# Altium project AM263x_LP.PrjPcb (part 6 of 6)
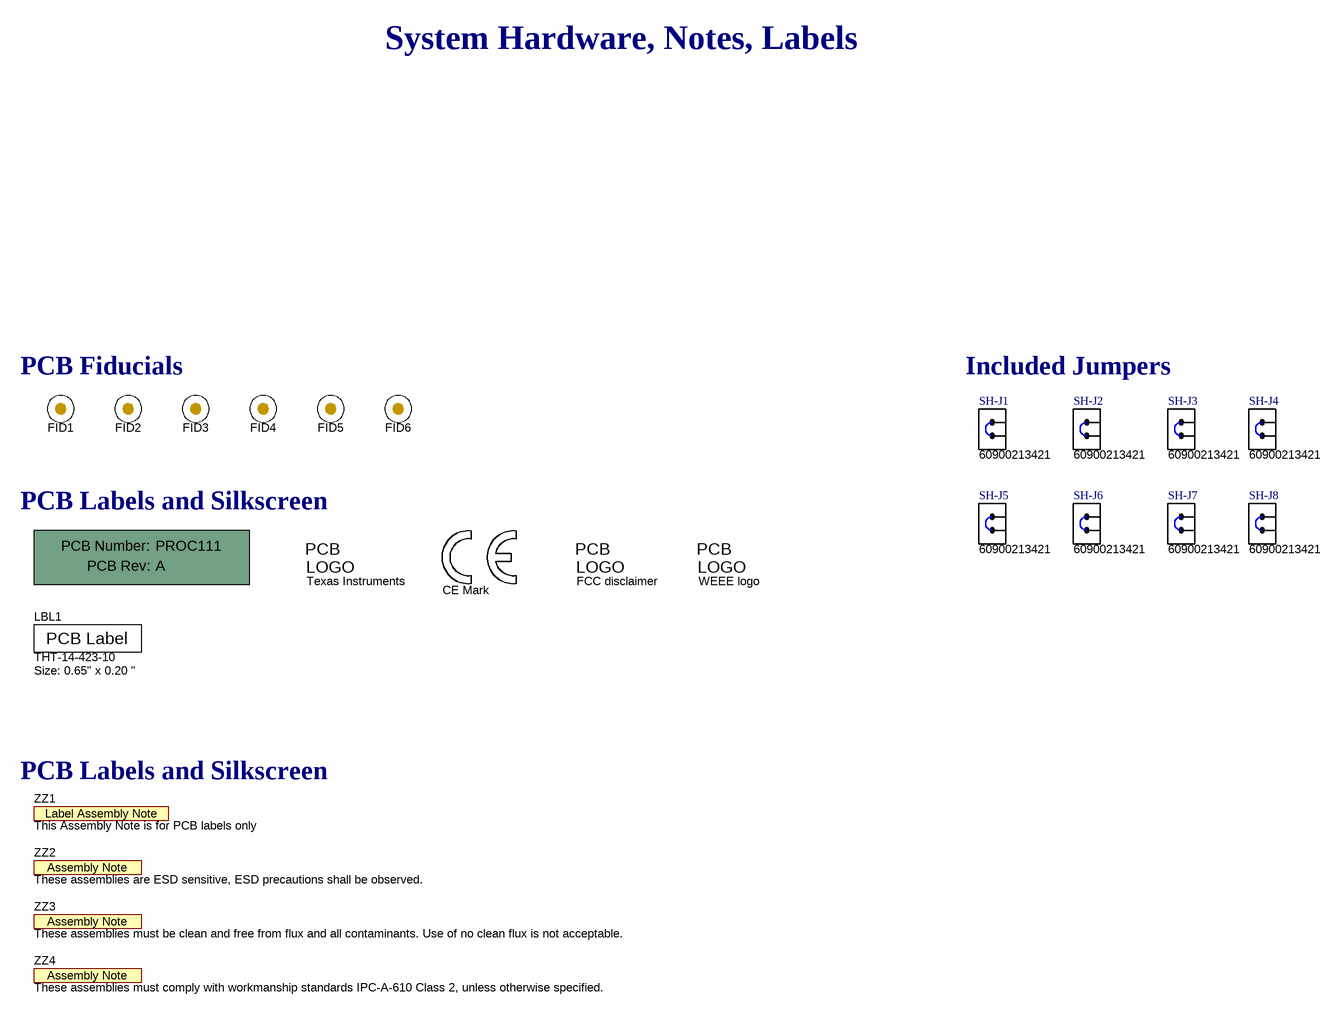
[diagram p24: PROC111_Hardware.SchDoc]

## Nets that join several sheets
GND: PROC111_System_Power_1 (34 pins), PROC111_System_Power_2 (48 pins), PROC111_AM263x_1_Power (147 pins), PROC111_AM263x_2_Clock_Reset_Boot_JTAG (30 pins), PROC111_AM263x_3_QSPI_MMC (17 pins), PROC111_AM263x_4_ADC_DAC (35 pins), PROC111_AM263x_6_RGMII_MII (C100.1 U17.3), PROC111_AM263x_7_PRU (11 pins), PROC111_Push_Buttons (13 pins), PROC111_Test_Automation (19 pins), PROC111_Ehernet_PHY_1 (41 pins), PROC111_Ehernet_PHY_2 (35 pins), PROC111_Ehernet_RJ45_1 (10 pins), PROC111_Ehernet_RJ45_2 (10 pins), PROC111_Boosterpack_Headers (12 pins), PROC111_Breakout_Headers (31 pins), PROC111_XDS110_2 (7 pins), PROC111_LED (14 pins)
GND_XDS: PROC111_XDS110_1 (14 pins), PROC111_XDS110_2 (44 pins)
VBUS_XDS_5V0: PROC111_XDS110_1 (7 pins), PROC111_XDS110_2 (R132.2 R136.2)
VDD_AM263_1V2: PROC111_System_Power_2 (7 pins), PROC111_AM263x_1_Power (49 pins)
VDD_ETH_1V1: PROC111_System_Power_2 (6 pins), PROC111_Ehernet_PHY_1 (FB3.1), PROC111_Ehernet_PHY_2 (FB5.1)
VDD_ETH_2V5: PROC111_System_Power_2 (6 pins), PROC111_Ehernet_PHY_1 (FB4.1), PROC111_Ehernet_PHY_2 (FB6.1)
VDD_XDS3V3: PROC111_XDS110_1 (7 pins), PROC111_XDS110_2 (36 pins)
VDDA_AM263_1V8_LDO: PROC111_AM263x_1_Power (9 pins), PROC111_AM263x_4_ADC_DAC (S1.1)
VPP_AM263_1V7: PROC111_System_Power_2 (C253.1 R372.2 U53.5), PROC111_AM263x_1_Power (R376.2)
VSYS_3V3: PROC111_System_Power_1 (J12.1), PROC111_System_Power_2 (11 pins), PROC111_AM263x_1_Power (20 pins), PROC111_AM263x_2_Clock_Reset_Boot_JTAG (14 pins), PROC111_AM263x_Serial_Connectivity (R175.2 R176.2), PROC111_AM263x_3_QSPI_MMC (15 pins), PROC111_AM263x_5_ePWM_eQEP_FSI (R55.2 R56.2), PROC111_AM263x_6_RGMII_MII (C100.2 R63.2 R64.2 U17.8), PROC111_AM263x_7_PRU (14 pins), PROC111_Push_Buttons (8 pins), PROC111_Test_Automation (U35.1 U35.5), PROC111_Ehernet_PHY_1 (26 pins), PROC111_Ehernet_PHY_2 (18 pins), PROC111_Ehernet_RJ45_1 (R224.1 R226.2 R228.2), PROC111_Ehernet_RJ45_2 (R230.1 R232.2 R234.2), PROC111_Boosterpack_Headers (11 pins), PROC111_Breakout_Headers (8 pins), PROC111_XDS110_2 (6 pins), PROC111_LED (17 pins)
VSYS_5V0: PROC111_System_Power_1 (5 pins), PROC111_System_Power_2 (26 pins), PROC111_AM263x_1_Power (R1.2), PROC111_Breakout_Headers (16 pins), PROC111_LED (R257.2 R265.2 R302.2)
VSYS_TA_3V3: PROC111_AM263x_2_Clock_Reset_Boot_JTAG (12 pins), PROC111_Test_Automation (23 pins), PROC111_LED (R315.2)
VUSB_5V0: PROC111_System_Power_1 (19 pins), PROC111_Test_Automation (C187.1 C188.1 R193.2 U36.2), PROC111_Boosterpack_Headers (J10.1 J14.1)
ADC_EXT_VREF: PROC111_AM263x_4_ADC_DAC (S2.3 S2.6), PROC111_Breakout_Headers (J17.2)
AM263_ADC0_AIN0: PROC111_AM263x_4_ADC_DAC (R340.1 U12.1 U12.10), PROC111_Boosterpack_Headers (J1/J3.23)
AM263_ADC0_AIN1: PROC111_AM263x_4_ADC_DAC (R341.1 U13.2 U13.9), PROC111_Boosterpack_Headers (J1/J3.28)
AM263_ADC0_AIN2: PROC111_AM263x_4_ADC_DAC (R342.1), PROC111_Boosterpack_Headers (U52.32)
AM263_ADC0_AIN2_LIN1_TXD: PROC111_AM263x_4_ADC_DAC (U14.5 U14.6), PROC111_Boosterpack_Headers (J5/J7.66 U52.7)
AM263_ADC0_AIN3: PROC111_AM263x_4_ADC_DAC (R343.1 U13.5 U13.6), PROC111_Boosterpack_Headers (J1/J3.2)
AM263_ADC1_AIN0: PROC111_AM263x_4_ADC_DAC (R344.1 U12.2 U12.9), PROC111_Boosterpack_Headers (J1/J3.24)
AM263_ADC1_AIN1: PROC111_AM263x_4_ADC_DAC (R345.1 U13.4 U13.7), PROC111_Boosterpack_Headers (J1/J3.29)
AM263_ADC1_AIN2: PROC111_AM263x_4_ADC_DAC (R346.1), PROC111_Boosterpack_Headers (U52.29)
AM263_ADC1_AIN2_SDFM0_D2: PROC111_AM263x_4_ADC_DAC (U15.1 U15.10), PROC111_Boosterpack_Headers (J5/J7.67 U52.11)
AM263_ADC1_AIN3: PROC111_AM263x_4_ADC_DAC (D16.1 R347.1), PROC111_Boosterpack_Headers (J1/J3.6)
AM263_ADC2_AIN0: PROC111_AM263x_4_ADC_DAC (R348.1 U12.4 U12.7), PROC111_Boosterpack_Headers (J1/J3.25)
AM263_ADC2_AIN1: PROC111_AM263x_4_ADC_DAC (R349.1), PROC111_Boosterpack_Headers (U52.38)
AM263_ADC2_AIN1_MCAN1_RX: PROC111_AM263x_4_ADC_DAC (U14.1 U14.10), PROC111_Boosterpack_Headers (J5/J7.63 U52.4)
AM263_ADC2_AIN2: PROC111_AM263x_4_ADC_DAC (R350.1), PROC111_Boosterpack_Headers (U52.27)
AM263_ADC2_AIN2_SDFM0_CLK2: PROC111_AM263x_4_ADC_DAC (U15.2 U15.9), PROC111_Boosterpack_Headers (J5/J7.68 U52.12)
AM263_ADC2_AIN3: PROC111_AM263x_4_ADC_DAC (R351.1 U15.5 U15.6), PROC111_Boosterpack_Headers (J5/J7.42)
AM263_ADC3_AIN0: PROC111_AM263x_4_ADC_DAC (R352.1 U12.5 U12.6), PROC111_Boosterpack_Headers (J1/J3.26)
AM263_ADC3_AIN1: PROC111_AM263x_4_ADC_DAC (R353.1), PROC111_Boosterpack_Headers (U52.36)
AM263_ADC3_AIN1_MCAN1_TX: PROC111_AM263x_4_ADC_DAC (U14.2 U14.9), PROC111_Boosterpack_Headers (J5/J7.64 U52.5)
AM263_ADC3_AIN2: PROC111_AM263x_4_ADC_DAC (R354.1), PROC111_Boosterpack_Headers (U52.25)
AM263_ADC3_AIN2_SDFM0_D3: PROC111_AM263x_4_ADC_DAC (U15.4 U15.7), PROC111_Boosterpack_Headers (J5/J7.69 U52.13)
AM263_ADC3_AIN3: PROC111_AM263x_4_ADC_DAC (D15.1 R355.1), PROC111_Boosterpack_Headers (J5/J7.46)
AM263_ADC4_AIN0: PROC111_AM263x_4_ADC_DAC (R356.1 R358.1 U13.1 U13.10), PROC111_Boosterpack_Headers (J1/J3.27)
AM263_ADC4_AIN1: PROC111_AM263x_4_ADC_DAC (R357.1 R359.1), PROC111_Boosterpack_Headers (U52.34)
AM263_ADC4_AIN1_LIN1_RXD: PROC111_AM263x_4_ADC_DAC (U14.4 U14.7), PROC111_Boosterpack_Headers (J5/J7.65 U52.6)
AM263_BP_MUX_SEL_GPIO63: PROC111_AM263x_5_ePWM_eQEP_FSI (U1.G4), PROC111_Boosterpack_Headers (5 pins)
AM263_CAN_STB_GPIO51: PROC111_AM263x_5_ePWM_eQEP_FSI (U1.D1), PROC111_Breakout_Headers (R248.2)
AM263_CLKOUT0: PROC111_AM263x_2_Clock_Reset_Boot_JTAG (R4.2 TP1.1), PROC111_Ehernet_PHY_1 (R118.1)
AM263_DAC_OUT1: PROC111_AM263x_4_ADC_DAC (R45.1), PROC111_Boosterpack_Headers (J1/J3.30)
AM263_DAC_OUT2: PROC111_AM263x_4_ADC_DAC (R3.1), PROC111_Boosterpack_Headers (U52.23)
AM263_EPWM0_A: PROC111_AM263x_5_ePWM_eQEP_FSI (R46.1), PROC111_Boosterpack_Headers (J2/J4.11)
AM263_EPWM0_B: PROC111_AM263x_5_ePWM_eQEP_FSI (R47.1), PROC111_Boosterpack_Headers (J6/J8.59)
AM263_EPWM1_A: PROC111_AM263x_5_ePWM_eQEP_FSI (R48.1), PROC111_Boosterpack_Headers (J2/J4.37)
AM263_EPWM1_B: PROC111_AM263x_5_ePWM_eQEP_FSI (R49.1), PROC111_Boosterpack_Headers (J2/J4.38)
AM263_EPWM2_A: PROC111_AM263x_5_ePWM_eQEP_FSI (R50.1), PROC111_Boosterpack_Headers (J2/J4.39)
AM263_EPWM2_B: PROC111_AM263x_5_ePWM_eQEP_FSI (R51.1), PROC111_Boosterpack_Headers (J2/J4.40)
AM263_EPWM3_A: PROC111_AM263x_5_ePWM_eQEP_FSI (R52.1), PROC111_Boosterpack_Headers (J6/J8.77)
AM263_EPWM3_B: PROC111_AM263x_5_ePWM_eQEP_FSI (R53.1), PROC111_Boosterpack_Headers (J6/J8.78)
AM263_EPWM9_A: PROC111_AM263x_5_ePWM_eQEP_FSI (R9.1), PROC111_Boosterpack_Headers (J6/J8.75)
AM263_EPWM9_B: PROC111_AM263x_5_ePWM_eQEP_FSI (R12.1), PROC111_Boosterpack_Headers (J6/J8.76)
AM263_EPWM11_A: PROC111_AM263x_5_ePWM_eQEP_FSI (R13.1), PROC111_Boosterpack_Headers (J6/J8.51)
AM263_EPWM11_B: PROC111_AM263x_5_ePWM_eQEP_FSI (R99.1), PROC111_Boosterpack_Headers (J6/J8.52)
AM263_EPWM12_A: PROC111_AM263x_5_ePWM_eQEP_FSI (R280.1), PROC111_Boosterpack_Headers (J6/J8.53)
AM263_EPWM12_B: PROC111_AM263x_5_ePWM_eQEP_FSI (R281.1), PROC111_Boosterpack_Headers (J6/J8.57)
AM263_EPWM13_A: PROC111_AM263x_5_ePWM_eQEP_FSI (R59.1), PROC111_Boosterpack_Headers (J6/J8.79)
AM263_EPWM13_B: PROC111_AM263x_5_ePWM_eQEP_FSI (R60.1), PROC111_Boosterpack_Headers (J6/J8.80)
AM263_EPWM14_A: PROC111_AM263x_5_ePWM_eQEP_FSI (R282.1), PROC111_Boosterpack_Headers (J2/J4.35)
AM263_EPWM14_B: PROC111_AM263x_5_ePWM_eQEP_FSI (R283.1), PROC111_Boosterpack_Headers (J2/J4.36)
AM263_EPWM15_A: PROC111_AM263x_5_ePWM_eQEP_FSI (R284.1), PROC111_Boosterpack_Headers (J2/J4.34)
AM263_EPWM15_B: PROC111_AM263x_5_ePWM_eQEP_FSI (R285.1), PROC111_Boosterpack_Headers (J5/J7.45)
AM263_EQEP0_A: PROC111_AM263x_5_ePWM_eQEP_FSI (U1.B14), PROC111_Breakout_Headers (R328.1)
AM263_EQEP0_B: PROC111_AM263x_5_ePWM_eQEP_FSI (U1.A14), PROC111_Breakout_Headers (R329.1)
AM263_EQEP0_INDEX: PROC111_AM263x_5_ePWM_eQEP_FSI (U1.D11), PROC111_Breakout_Headers (R330.1)
AM263_EQEP0_STROBE: PROC111_AM263x_5_ePWM_eQEP_FSI (U1.C12), PROC111_Breakout_Headers (R331.1)
AM263_EQEP2_A: PROC111_AM263x_Serial_Connectivity (U1.B13), PROC111_Breakout_Headers (R332.1)
AM263_EQEP2_B: PROC111_AM263x_Serial_Connectivity (U1.A13), PROC111_Breakout_Headers (R333.1)
AM263_EQEP2_INDEX: PROC111_AM263x_Serial_Connectivity (U1.A12), PROC111_Breakout_Headers (R334.1)
AM263_EQEP2_STROBE: PROC111_AM263x_Serial_Connectivity (U1.B12), PROC111_Breakout_Headers (R335.1)
AM263_FSIRX1_CLK: PROC111_AM263x_5_ePWM_eQEP_FSI (U1.E1), PROC111_Breakout_Headers (J23.1)
AM263_FSIRX1_DATA0: PROC111_AM263x_5_ePWM_eQEP_FSI (U1.F3), PROC111_Breakout_Headers (J23.5)
AM263_FSIRX1_DATA1: PROC111_AM263x_5_ePWM_eQEP_FSI (U1.F4), PROC111_Breakout_Headers (J23.7)
AM263_FSITX1_CLK: PROC111_AM263x_5_ePWM_eQEP_FSI (R54.1), PROC111_Breakout_Headers (J23.2)
AM263_FSITX1_DATA0: PROC111_AM263x_5_ePWM_eQEP_FSI (R57.1), PROC111_Breakout_Headers (J23.6)
AM263_FSITX1_DATA1: PROC111_AM263x_5_ePWM_eQEP_FSI (R58.1), PROC111_Breakout_Headers (J23.8)
AM263_I2C1_SCL: PROC111_AM263x_2_Clock_Reset_Boot_JTAG (U16.6), PROC111_AM263x_Serial_Connectivity (R175.1 U1.D7), PROC111_Boosterpack_Headers (J5/J7.49), PROC111_LED (U48.15)
AM263_I2C1_SDA: PROC111_AM263x_2_Clock_Reset_Boot_JTAG (U16.5), PROC111_AM263x_Serial_Connectivity (R176.1 U1.C8), PROC111_Boosterpack_Headers (J5/J7.50), PROC111_LED (U48.2)
AM263_I2C3_SCL: PROC111_AM263x_5_ePWM_eQEP_FSI (R55.1 U1.H2), PROC111_Test_Automation (U35.2), PROC111_Boosterpack_Headers (J1/J3.9)
AM263_I2C3_SDA: PROC111_AM263x_5_ePWM_eQEP_FSI (R56.1 U1.G3), PROC111_Test_Automation (U35.3), PROC111_Boosterpack_Headers (J1/J3.10)
AM263_ICSSM_MII0_COL: PROC111_AM263x_7_PRU (U49.11), PROC111_Ehernet_PHY_2 (R207.1 R219.2 U37.45), PROC111_Ehernet_RJ45_2 (R231.2)
AM263_ICSSM_MII0_RXCLK: PROC111_AM263x_7_PRU (U23.32), PROC111_Ehernet_PHY_2 (R196.1)
AM263_ICSSM_MII0_RXD0: PROC111_AM263x_7_PRU (U23.41), PROC111_Ehernet_PHY_2 (R198.1 R203.1 R215.2)
AM263_ICSSM_MII0_RXD1: PROC111_AM263x_7_PRU (U23.39), PROC111_Ehernet_PHY_2 (R199.1 R204.1 R216.2)
AM263_ICSSM_MII0_RXD2: PROC111_AM263x_7_PRU (U23.38), PROC111_Ehernet_PHY_2 (R200.1 R210.1 R222.2)
AM263_ICSSM_MII0_RXD3: PROC111_AM263x_7_PRU (U23.36), PROC111_Ehernet_PHY_2 (R201.1 R211.1 R223.2)
AM263_ICSSM_MII0_RXDV: PROC111_AM263x_7_PRU (U23.34), PROC111_Ehernet_PHY_2 (R197.1 R205.1 R217.2)
AM263_ICSSM_MII0_RXER: PROC111_AM263x_7_PRU (U49.2), PROC111_Ehernet_PHY_2 (R206.1 R218.2 U37.46), PROC111_Ehernet_RJ45_2 (R235.2)
AM263_ICSSM_MII0_RXLINK: PROC111_AM263x_7_PRU (U49.5), PROC111_Ehernet_PHY_2 (R208.1 R220.2 U37.47), PROC111_Ehernet_RJ45_2 (R233.2)
AM263_ICSSM_MII0_TXCLK: PROC111_AM263x_7_PRU (U23.19), PROC111_Ehernet_PHY_2 (U37.29)
AM263_ICSSM_MII0_TXD0: PROC111_AM263x_7_PRU (U23.29), PROC111_Ehernet_PHY_2 (U37.28)
AM263_ICSSM_MII0_TXD1: PROC111_AM263x_7_PRU (U23.27), PROC111_Ehernet_PHY_2 (U37.27)
AM263_ICSSM_MII0_TXD2: PROC111_AM263x_7_PRU (U23.25), PROC111_Ehernet_PHY_2 (U37.26)
AM263_ICSSM_MII0_TXD3: PROC111_AM263x_7_PRU (U23.23), PROC111_Ehernet_PHY_2 (U37.25)
AM263_ICSSM_MII0_TXEN: PROC111_AM263x_7_PRU (U23.21), PROC111_Ehernet_PHY_2 (U37.37)
AM263_ICSSM_MII1_COL: PROC111_AM263x_7_PRU (U1.C18), PROC111_Ehernet_PHY_1 (R112.1 R124.2 U22.45), PROC111_Ehernet_RJ45_1 (R225.2)
AM263_ICSSM_MII1_RXCLK: PROC111_AM263x_7_PRU (U1.E16), PROC111_Ehernet_PHY_1 (U50.31)
AM263_ICSSM_MII1_RXD0: PROC111_AM263x_7_PRU (U1.F18), PROC111_Ehernet_PHY_1 (U50.42)
AM263_ICSSM_MII1_RXD1: PROC111_AM263x_7_PRU (U1.G16), PROC111_Ehernet_PHY_1 (U50.40)
AM263_ICSSM_MII1_RXD2: PROC111_AM263x_7_PRU (U1.E17), PROC111_Ehernet_PHY_1 (U50.37)
AM263_ICSSM_MII1_RXD3: PROC111_AM263x_7_PRU (U1.E18), PROC111_Ehernet_PHY_1 (U50.35)
AM263_ICSSM_MII1_RXDV: PROC111_AM263x_7_PRU (U1.F16), PROC111_Ehernet_PHY_1 (U50.33)
AM263_ICSSM_MII1_RXER: PROC111_AM263x_7_PRU (U1.F15), PROC111_Ehernet_PHY_1 (R111.1 R123.2 U22.46), PROC111_Ehernet_RJ45_1 (R229.2)
AM263_ICSSM_MII1_RXLINK: PROC111_AM263x_7_PRU (U1.D18), PROC111_Ehernet_PHY_1 (R110.1 R122.2 U22.47), PROC111_Ehernet_RJ45_1 (R227.2)
AM263_ICSSM_MII1_TXCLK: PROC111_AM263x_7_PRU (R86.1), PROC111_Ehernet_PHY_1 (U50.18)
AM263_ICSSM_MII1_TXD0: PROC111_AM263x_7_PRU (R81.1), PROC111_Ehernet_PHY_1 (U50.28)
AM263_ICSSM_MII1_TXD1: PROC111_AM263x_7_PRU (R82.1), PROC111_Ehernet_PHY_1 (U50.26)
AM263_ICSSM_MII1_TXD2: PROC111_AM263x_7_PRU (R83.1), PROC111_Ehernet_PHY_1 (U50.24)
AM263_ICSSM_MII1_TXD3: PROC111_AM263x_7_PRU (R84.1), PROC111_Ehernet_PHY_1 (U50.22)
AM263_ICSSM_MII1_TXEN: PROC111_AM263x_7_PRU (R85.1), PROC111_Ehernet_PHY_1 (U50.20)
AM263_IEP0_EDC_SYNC_OUT0: PROC111_AM263x_7_PRU (R88.1), PROC111_Boosterpack_Headers (J6/J8.72)
AM263_IEP0_EDIO_DATA_IN_OUT31: PROC111_AM263x_7_PRU (R87.1), PROC111_Boosterpack_Headers (J6/J8.71)
AM263_INT1_PB_GPIO123: PROC111_AM263x_8_SDFM (U1.D14), PROC111_Push_Buttons (U34.4)
AM263_LED_ENABLE_GPIO25: PROC111_AM263x_Serial_Connectivity (U1.C7), PROC111_LED (R278.2 U48.8)
AM263_LED_GPIO26: PROC111_AM263x_Serial_Connectivity (U1.B7), PROC111_LED (R303.1 R304.2)
AM263_LIN1_RXD: PROC111_AM263x_Serial_Connectivity (U1.A9), PROC111_Boosterpack_Headers (U52.33)
AM263_LIN1_TXD: PROC111_AM263x_Serial_Connectivity (R297.1), PROC111_Boosterpack_Headers (U52.31)
AM263_LIN2_RXD: PROC111_AM263x_Serial_Connectivity (U1.B8), PROC111_Boosterpack_Headers (U52.41)
AM263_LIN2_TXD: PROC111_AM263x_Serial_Connectivity (R166.1), PROC111_Boosterpack_Headers (U52.39)
AM263_MCAN0_RX: PROC111_AM263x_Serial_Connectivity (U1.M1), PROC111_Breakout_Headers (R249.1)
AM263_MCAN0_TX: PROC111_AM263x_Serial_Connectivity (R167.1), PROC111_Breakout_Headers (R245.1)
AM263_MCAN1_RX: PROC111_AM263x_Serial_Connectivity (U1.L2), PROC111_Boosterpack_Headers (U52.37)
AM263_MCAN1_TX: PROC111_AM263x_Serial_Connectivity (R168.1), PROC111_Boosterpack_Headers (U52.35)
AM263_MUX_EN_GPIO58: PROC111_AM263x_5_ePWM_eQEP_FSI (U1.F1), PROC111_AM263x_7_PRU (R288.2 R290.2 U23.8 U46.2), PROC111_Boosterpack_Headers (U52.8)
AM263_PORZ_PB: PROC111_AM263x_2_Clock_Reset_Boot_JTAG (U2.1), PROC111_Push_Buttons (U34.6)
AM263_PR0_MDIO0_MDC: PROC111_AM263x_6_RGMII_MII (U17.2), PROC111_AM263x_7_PRU (R71.1 R73.1)
AM263_PR0_MDIO0_MDIO: PROC111_AM263x_6_RGMII_MII (U17.4), PROC111_AM263x_7_PRU (R72.1 R74.1)
AM263_PRU_MUX_SEL_GPIO64: PROC111_AM263x_5_ePWM_eQEP_FSI (U1.J3), PROC111_AM263x_7_PRU (5 pins)
AM263_RESETN_PB: PROC111_AM263x_2_Clock_Reset_Boot_JTAG (R5.1), PROC111_Push_Buttons (R179.1 U33.4)
AM263_RGMII1_RD0: PROC111_AM263x_6_RGMII_MII (U1.U17), PROC111_Ehernet_PHY_1 (U50.41)
AM263_RGMII1_RD1: PROC111_AM263x_6_RGMII_MII (U1.T17), PROC111_Ehernet_PHY_1 (U50.39)
AM263_RGMII1_RD2: PROC111_AM263x_6_RGMII_MII (U1.U18), PROC111_Ehernet_PHY_1 (U50.38)
AM263_RGMII1_RD3: PROC111_AM263x_6_RGMII_MII (U1.T18), PROC111_Ehernet_PHY_1 (U50.36)
AM263_RGMII1_RX_CTL: PROC111_AM263x_6_RGMII_MII (U1.R18), PROC111_Ehernet_PHY_1 (U50.34)
AM263_RGMII1_RXC: PROC111_AM263x_6_RGMII_MII (U1.R17), PROC111_Ehernet_PHY_1 (U50.32)
AM263_RGMII1_TD0: PROC111_AM263x_6_RGMII_MII (R65.1), PROC111_Ehernet_PHY_1 (U50.29)
AM263_RGMII1_TD1: PROC111_AM263x_6_RGMII_MII (R66.1), PROC111_Ehernet_PHY_1 (U50.27)
AM263_RGMII1_TD2: PROC111_AM263x_6_RGMII_MII (R67.1), PROC111_Ehernet_PHY_1 (U50.25)
AM263_RGMII1_TD3: PROC111_AM263x_6_RGMII_MII (R68.1), PROC111_Ehernet_PHY_1 (U50.23)
AM263_RGMII1_TX_CTL: PROC111_AM263x_6_RGMII_MII (R69.1), PROC111_Ehernet_PHY_1 (U50.21)
AM263_RGMII1_TXC: PROC111_AM263x_6_RGMII_MII (R70.1), PROC111_Ehernet_PHY_1 (U50.19)
AM263_SAFETY_ERRORN: PROC111_AM263x_2_Clock_Reset_Boot_JTAG (R258.1 U1.D4), PROC111_LED (R268.1 R272.1)
AM263_SD_ENABLE_GPIO122: PROC111_AM263x_3_QSPI_MMC (U9.2), PROC111_AM263x_8_SDFM (U1.B16)
AM263_SDFM0_CLK1: PROC111_AM263x_8_SDFM (R369.1), PROC111_Boosterpack_Headers (J6/J8.74)
AM263_SDFM0_CLK2: PROC111_AM263x_8_SDFM (R370.1), PROC111_Boosterpack_Headers (U52.26)
AM263_SDFM0_CLK3: PROC111_AM263x_8_SDFM (R371.1), PROC111_Boosterpack_Headers (U52.22)
AM263_SDFM0_D2: PROC111_AM263x_8_SDFM (U1.C13), PROC111_Boosterpack_Headers (U52.28)
AM263_SDFM0_D3: PROC111_AM263x_8_SDFM (U1.C14), PROC111_Boosterpack_Headers (U52.24)
AM263_SFDM0_D1: PROC111_AM263x_8_SDFM (U1.D13), PROC111_Boosterpack_Headers (J6/J8.73)
AM263_SOP0: PROC111_AM263x_2_Clock_Reset_Boot_JTAG (U4.15), PROC111_AM263x_3_QSPI_MMC (R42.2)
AM263_SOP1: PROC111_AM263x_2_Clock_Reset_Boot_JTAG (U4.14), PROC111_AM263x_3_QSPI_MMC (R43.2)
AM263_SOP2: PROC111_AM263x_2_Clock_Reset_Boot_JTAG (U4.13), PROC111_AM263x_Serial_Connectivity (R173.2)
AM263_SOP3: PROC111_AM263x_2_Clock_Reset_Boot_JTAG (U4.12), PROC111_AM263x_Serial_Connectivity (R174.2)
AM263_SPI0_CLK: PROC111_AM263x_Serial_Connectivity (R169.1 R173.1), PROC111_Boosterpack_Headers (U51.2)
AM263_SPI0_CS0: PROC111_AM263x_Serial_Connectivity (U1.C11), PROC111_Boosterpack_Headers (U51.14)
AM263_SPI0_D0: PROC111_AM263x_Serial_Connectivity (R170.1 R174.1), PROC111_Boosterpack_Headers (J2/J4.15)
AM263_SPI0_D1: PROC111_AM263x_Serial_Connectivity (U1.B11), PROC111_Boosterpack_Headers (J2/J4.14)
AM263_SPI1_CLK: PROC111_AM263x_Serial_Connectivity (R171.1), PROC111_Boosterpack_Headers (J5/J7.47)
AM263_SPI1_CS0: PROC111_AM263x_Serial_Connectivity (U1.C9), PROC111_Boosterpack_Headers (J6/J8.58)
AM263_SPI1_D0: PROC111_AM263x_Serial_Connectivity (R172.1), PROC111_Boosterpack_Headers (U51.11)
AM263_SPI1_D1: PROC111_AM263x_Serial_Connectivity (U1.D9), PROC111_Boosterpack_Headers (U51.5)
AM263_TCK: PROC111_AM263x_2_Clock_Reset_Boot_JTAG (U1.B3), PROC111_XDS110_2 (R324.1)
AM263_TDI: PROC111_AM263x_2_Clock_Reset_Boot_JTAG (U1.C5), PROC111_XDS110_2 (R326.1)
AM263_TDO: PROC111_AM263x_2_Clock_Reset_Boot_JTAG (R7.2), PROC111_XDS110_2 (U26.3)
AM263_TMS: PROC111_AM263x_2_Clock_Reset_Boot_JTAG (U1.D5), PROC111_XDS110_2 (R325.1)
AM263_UART0_RXD: PROC111_AM263x_Serial_Connectivity (U1.A7), PROC111_XDS110_2 (R327.1)
AM263_UART0_TXD: PROC111_AM263x_Serial_Connectivity (R164.1), PROC111_XDS110_2 (U27.3)
AM263_UART1_RXD: PROC111_AM263x_Serial_Connectivity (U1.L3), PROC111_Boosterpack_Headers (J1/J3.3)
AM263_UART1_TXD: PROC111_AM263x_Serial_Connectivity (R165.1), PROC111_Boosterpack_Headers (J1/J3.4)
AM263_WARMRSTN: PROC111_AM263x_2_Clock_Reset_Boot_JTAG (R5.2 U1.C3), PROC111_AM263x_3_QSPI_MMC (U9.1), PROC111_Ehernet_PHY_1 (U22.43), PROC111_Ehernet_PHY_2 (U37.43)
BP_PORZ: PROC111_Push_Buttons (R180.2), PROC111_Boosterpack_Headers (J2/J4.16 J6/J8.56)
DAC_EXT_VREF: PROC111_AM263x_4_ADC_DAC (S1.3), PROC111_Breakout_Headers (J18.2)
ETH1_CLKOUT: PROC111_Ehernet_PHY_1 (R106.2), PROC111_Ehernet_PHY_2 (R213.1)
ETH1_TD_A_N: PROC111_Ehernet_PHY_1 (U22.2), PROC111_Ehernet_RJ45_1 (J7.10 U38.2 U38.9)
ETH1_TD_A_P: PROC111_Ehernet_PHY_1 (U22.1), PROC111_Ehernet_RJ45_1 (J7.9 U38.1 U38.10)
ETH1_TD_B_N: PROC111_Ehernet_PHY_1 (U22.5), PROC111_Ehernet_RJ45_1 (J7.8 U38.5 U38.6)
ETH1_TD_B_P: PROC111_Ehernet_PHY_1 (U22.4), PROC111_Ehernet_RJ45_1 (J7.7 U38.4 U38.7)
ETH1_TD_C_N: PROC111_Ehernet_PHY_1 (U22.8), PROC111_Ehernet_RJ45_1 (J7.6 U39.2 U39.9)
ETH1_TD_C_P: PROC111_Ehernet_PHY_1 (U22.7), PROC111_Ehernet_RJ45_1 (J7.5 U39.1 U39.10)
ETH1_TD_D_N: PROC111_Ehernet_PHY_1 (U22.11), PROC111_Ehernet_RJ45_1 (J7.4 U39.5 U39.6)
ETH1_TD_D_P: PROC111_Ehernet_PHY_1 (U22.10), PROC111_Ehernet_RJ45_1 (J7.3 U39.4 U39.7)
ETH2_TD_A_N: PROC111_Ehernet_PHY_2 (U37.2), PROC111_Ehernet_RJ45_2 (J8.10 U40.2 U40.9)
ETH2_TD_A_P: PROC111_Ehernet_PHY_2 (U37.1), PROC111_Ehernet_RJ45_2 (J8.9 U40.1 U40.10)
ETH2_TD_B_N: PROC111_Ehernet_PHY_2 (U37.5), PROC111_Ehernet_RJ45_2 (J8.8 U40.5 U40.6)
ETH2_TD_B_P: PROC111_Ehernet_PHY_2 (U37.4), PROC111_Ehernet_RJ45_2 (J8.7 U40.4 U40.7)
ETH2_TD_C_N: PROC111_Ehernet_PHY_2 (U37.8), PROC111_Ehernet_RJ45_2 (J8.6 U41.2 U41.9)
ETH2_TD_C_P: PROC111_Ehernet_PHY_2 (U37.7), PROC111_Ehernet_RJ45_2 (J8.5 U41.1 U41.10)
ETH2_TD_D_N: PROC111_Ehernet_PHY_2 (U37.11), PROC111_Ehernet_RJ45_2 (J8.4 U41.5 U41.6)
ETH2_TD_D_P: PROC111_Ehernet_PHY_2 (U37.10), PROC111_Ehernet_RJ45_2 (J8.3 U41.4 U41.7)
MDIO_CLOCK: PROC111_AM263x_6_RGMII_MII (U17.10), PROC111_Ehernet_PHY_1 (U22.42), PROC111_Ehernet_PHY_2 (U37.42)
MDIO_DATA: PROC111_AM263x_6_RGMII_MII (U17.6), PROC111_Ehernet_PHY_1 (U22.41), PROC111_Ehernet_PHY_2 (U37.41)
MUX_EN_GPIO58_INV: PROC111_AM263x_7_PRU (R96.2 U46.4 U49.15), PROC111_Boosterpack_Headers (U51.15)
PG_VDD_1V2: PROC111_System_Power_2 (R295.1 U29.5), PROC111_AM263x_2_Clock_Reset_Boot_JTAG (U2.3), PROC111_LED (R317.1)
PG_VSYS_3V3: PROC111_System_Power_2 (R296.1 U32.5), PROC111_AM263x_2_Clock_Reset_Boot_JTAG (U2.6)
PR0_PRU0_GPIO0_MUX: PROC111_AM263x_7_PRU (U23.42), PROC111_Boosterpack_Headers (J2/J4.33)
PR0_PRU0_GPIO1_MUX: PROC111_AM263x_7_PRU (U23.40), PROC111_Boosterpack_Headers (J2/J4.32)
PR0_PRU0_GPIO2_MUX: PROC111_AM263x_7_PRU (U23.37), PROC111_Boosterpack_Headers (J2/J4.31)
PR0_PRU0_GPIO3_MUX: PROC111_AM263x_7_PRU (U23.35), PROC111_Boosterpack_Headers (J2/J4.19)
PR0_PRU0_GPIO4_MUX: PROC111_AM263x_7_PRU (U23.33), PROC111_Boosterpack_Headers (J2/J4.17)
PR0_PRU0_GPIO5_MUX: PROC111_AM263x_7_PRU (U49.3), PROC111_Boosterpack_Headers (J2/J4.13)
PR0_PRU0_GPIO6_MUX: PROC111_AM263x_7_PRU (U23.31), PROC111_Boosterpack_Headers (J5/J7.48)
PR0_PRU0_GPIO8_MUX: PROC111_AM263x_7_PRU (U49.6), PROC111_Boosterpack_Headers (U51.13)
PR0_PRU0_GPIO9_MUX: PROC111_AM263x_7_PRU (U49.10), PROC111_Boosterpack_Headers (U52.40)
PR0_PRU0_GPIO10_MUX: PROC111_AM263x_7_PRU (U49.13), PROC111_Boosterpack_Headers (J1/J3.8)
PR0_PRU0_GPIO11_MUX: PROC111_AM263x_7_PRU (U23.28), PROC111_Boosterpack_Headers (U52.42)
PR0_PRU0_GPIO12_MUX: PROC111_AM263x_7_PRU (U23.26), PROC111_Boosterpack_Headers (J1/J3.5)
PR0_PRU0_GPIO13_MUX: PROC111_AM263x_7_PRU (U23.24), PROC111_Boosterpack_Headers (U51.10)
PR0_PRU0_GPIO14_MUX: PROC111_AM263x_7_PRU (U23.22), PROC111_Boosterpack_Headers (U51.6)
PR0_PRU0_GPIO15_MUX: PROC111_AM263x_7_PRU (U23.20), PROC111_Boosterpack_Headers (J2/J4.12)
PR0_PRU0_GPIO16_MUX: PROC111_AM263x_7_PRU (U23.18), PROC111_Boosterpack_Headers (U51.3)
RGMII1_ICSSM_MUX_EN_GPIO1: PROC111_AM263x_3_QSPI_MMC (U1.R3), PROC111_Ehernet_PHY_1 (R292.2 R294.2 U50.8)
RGMII1_ICSSM_MUX_SEL_GPIO105: PROC111_AM263x_6_RGMII_MII (U17.1 U17.5), PROC111_AM263x_7_PRU (U1.D17), PROC111_Ehernet_PHY_1 (R291.2 R293.2 U50.9 U50.10)
RJ45_1_VCC: PROC111_Ehernet_RJ45_1 (J7.2 TP21.1), PROC111_Ehernet_RJ45_2 (J8.2 TP22.1)
TA_GPIO1: PROC111_Push_Buttons (Q3.1), PROC111_Test_Automation (J6.30 R185.2)
TA_GPIO3: PROC111_AM263x_2_Clock_Reset_Boot_JTAG (U5.1), PROC111_Test_Automation (J1.2 J6.32 R183.2)
TA_GPIO4: PROC111_AM263x_2_Clock_Reset_Boot_JTAG (U3.1), PROC111_Test_Automation (J6.33 R182.2)
TA_I2C_SCL: PROC111_AM263x_2_Clock_Reset_Boot_JTAG (U3.12), PROC111_Test_Automation (J6.37 R191.1)
TA_I2C_SDA: PROC111_AM263x_2_Clock_Reset_Boot_JTAG (U3.13), PROC111_Test_Automation (J6.39 R189.1)
TA_PORZ: PROC111_Push_Buttons (Q1.1 R180.1), PROC111_Test_Automation (J6.27 R187.2)
TA_POWERDOWNZ: PROC111_System_Power_1 (U47.2), PROC111_Test_Automation (J6.26 R188.2)
TA_RESETZ: PROC111_Push_Buttons (Q2.1), PROC111_Test_Automation (J6.28 R186.2)
XDSET_1_D_N: PROC111_XDS110_1 (J34.2 U44.1 U44.10), PROC111_XDS110_2 (U24.93)
XDSET_1_D_P: PROC111_XDS110_1 (J34.3 U44.2 U44.9), PROC111_XDS110_2 (U24.94)
XDSET_1_ID: PROC111_XDS110_1 (J34.4 U44.4 U44.7), PROC111_XDS110_2 (R130.1)

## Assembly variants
001: not fitted C89 C229 R3 R32 R109 R110 R111 R112 R113 R114 R115 R116 R118 R120 R121 R122 R123 R124 R125 R127 R128 R130 R203 R205 R206 R207 R208 R209 R210 R211 R213 R215 R216 R217 R218 R219 R220 R222 R223 R250 R261 R269 R270 R274 R287 R290 R291 R292 R298 R308 R309 R310 R320 R321 R322 R358 R359 R377 R378 R? R?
